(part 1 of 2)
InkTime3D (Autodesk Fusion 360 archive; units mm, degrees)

design "InkTime3D" references "Baterie", "WearAwareNewCase", "Shaker", "project-tsc", "Display_ePaper"
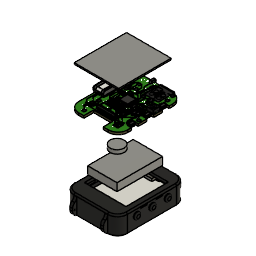
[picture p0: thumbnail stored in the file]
part number: 2026-04-19-21-12-50-660
component_insert "Component Insert1"
component_insert "Component Insert2"
component_insert "Component Insert3"
component_insert "Component Insert4"
component_insert "Component Insert5"

design "BST-BMV080-CAD"
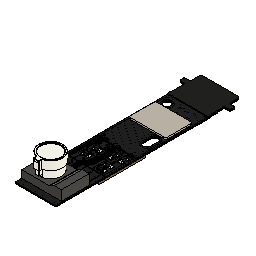
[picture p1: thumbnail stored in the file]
description: Part Number
part number: BMV080_MELTED
base_feature "Base Feature"

design "Display_ePaper"
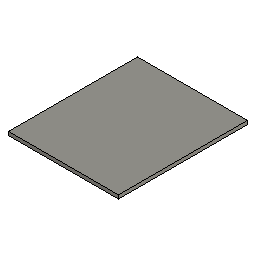
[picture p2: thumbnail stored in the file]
description: Part Number
part number: 2026-04-18-22-15-39-425
base_feature "Base Feature"

design "project-tsc"
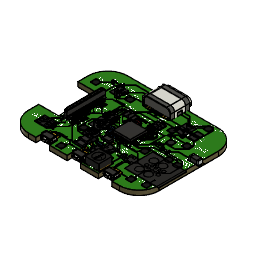
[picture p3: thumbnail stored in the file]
part number: 2026-04-17-17-33-59-124
part number: 2026-04-17-17-34-06-776
part number: 2026-04-17-17-34-07-423
part number: 2026-04-17-17-34-07-496
part number: 2026-04-17-17-34-07-570
part number: 2026-04-17-17-34-07-659
part number: 2026-04-17-17-34-07-837
part number: 2026-04-17-17-34-11-380
part number: 2026-04-17-17-34-11-386
part number: 2026-04-17-17-34-11-391
part number: 2026-04-17-17-34-11-420
part number: 2026-04-17-17-34-11-430
part number: 2026-04-17-17-34-11-437
part number: 2026-04-17-17-34-11-452
part number: 2026-04-17-17-34-11-458
part number: 2026-04-17-17-34-11-462
part number: 2026-04-17-17-34-11-469
part number: 2026-04-17-17-34-11-491
part number: 2026-04-17-17-34-11-533
part number: 2026-04-17-17-34-11-542
sketch "Outline" plane through (0, 0, 0) normal (0, 0, 1) x axis (1, 0, 0)
  line L1 (8.23, 32.71) -> (5.63, 32.71)
  line L2 (8.23, 34.51) -> (8.23, 32.71)
  line L3 (13.03, 34.51) -> (8.23, 34.51)
  line L4 (13.03, 32.71) -> (13.03, 34.51)
  line L5 (19.23, 32.71) -> (13.03, 32.71)
  line L6 (19.23, 34.51) -> (19.23, 32.71)
  line L7 (24.03, 34.51) -> (19.23, 34.51)
  line L8 (24.03, 32.71) -> (24.03, 34.51)
  line L9 (30.23, 32.71) -> (24.03, 32.71)
  line L10 (30.23, 34.51) -> (30.23, 32.71)
  line L11 (35.03, 34.51) -> (30.23, 34.51)
  line L12 (35.03, 32.71) -> (35.03, 34.51)
  line L13 (37.63, 32.71) -> (35.03, 32.71)
  line L14 (44.63, 60.71) -> (44.63, 39.71)
  line L15 (5.63, 67.71) -> (37.63, 67.71)
  line L16 (-1.37, 57.11) -> (-1.37, 60.71)
  line L17 (5.63, 57.11) -> (-1.37, 57.11)
  line L18 (5.63, 43.31) -> (5.63, 57.11)
  line L19 (-1.37, 43.31) -> (5.63, 43.31)
  line L20 (-1.37, 39.71) -> (-1.37, 43.31)
  line L21 (17.2539, 61.6177) -> (17.2526, 61.646)
  line L22 (17.2576, 61.5896) -> (17.2539, 61.6177)
  line L23 (17.2637, 61.5619) -> (17.2576, 61.5896)
  line L24 (17.2722, 61.5348) -> (17.2637, 61.5619)
  line L25 (17.2831, 61.5087) -> (17.2722, 61.5348)
  line L26 (17.2962, 61.4835) -> (17.2831, 61.5087)
  line L27 (17.3114, 61.4596) -> (17.2962, 61.4835)
  line L28 (17.3287, 61.4371) -> (17.3114, 61.4596)
  line L29 (17.3478, 61.4162) -> (17.3287, 61.4371)
  line L30 (17.3687, 61.397) -> (17.3478, 61.4162)
  line L31 (17.3912, 61.3798) -> (17.3687, 61.397)
  line L32 (17.4151, 61.3645) -> (17.3912, 61.3798)
  line L33 (17.4403, 61.3515) -> (17.4151, 61.3645)
  line L34 (17.4665, 61.3406) -> (17.4403, 61.3515)
  line L35 (17.4935, 61.3321) -> (17.4665, 61.3406)
  line L36 (17.5212, 61.3259) -> (17.4935, 61.3321)
  line L37 (17.5493, 61.3222) -> (17.5212, 61.3259)
  line L38 (17.5776, 61.321) -> (17.5493, 61.3222)
  line L39 (17.606, 61.3222) -> (17.5776, 61.321)
  line L40 (17.6341, 61.3259) -> (17.606, 61.3222)
  line L41 (17.6618, 61.3321) -> (17.6341, 61.3259)
  line L42 (17.6888, 61.3406) -> (17.6618, 61.3321)
  line L43 (17.715, 61.3515) -> (17.6888, 61.3406)
  line L44 (17.7401, 61.3645) -> (17.715, 61.3515)
  line L45 (17.764, 61.3798) -> (17.7401, 61.3645)
  line L46 (17.7865, 61.397) -> (17.764, 61.3798)
  line L47 (17.8074, 61.4162) -> (17.7865, 61.397)
  line L48 (17.8266, 61.4371) -> (17.8074, 61.4162)
  line L49 (17.8439, 61.4596) -> (17.8266, 61.4371)
  line L50 (17.8591, 61.4835) -> (17.8439, 61.4596)
  line L51 (17.8722, 61.5087) -> (17.8591, 61.4835)
  line L52 (17.883, 61.5348) -> (17.8722, 61.5087)
  line L53 (17.8916, 61.5619) -> (17.883, 61.5348)
  line L54 (17.8977, 61.5896) -> (17.8916, 61.5619)
  line L55 (17.9014, 61.6177) -> (17.8977, 61.5896)
  line L56 (17.9026, 61.646) -> (17.9014, 61.6177)
  line L57 (17.9026, 62.746) -> (17.9026, 61.646)
  line L58 (17.9014, 62.7743) -> (17.9026, 62.746)
  line L59 (17.8977, 62.8024) -> (17.9014, 62.7743)
  line L60 (17.8916, 62.8301) -> (17.8977, 62.8024)
  line L61 (17.883, 62.8572) -> (17.8916, 62.8301)
  line L62 (17.8722, 62.8834) -> (17.883, 62.8572)
  line L63 (17.8591, 62.9085) -> (17.8722, 62.8834)
  line L64 (17.8439, 62.9324) -> (17.8591, 62.9085)
  line L65 (17.8266, 62.9549) -> (17.8439, 62.9324)
  line L66 (17.8074, 62.9758) -> (17.8266, 62.9549)
  line L67 (17.7865, 62.995) -> (17.8074, 62.9758)
  line L68 (17.764, 63.0122) -> (17.7865, 62.995)
  line L69 (17.7401, 63.0275) -> (17.764, 63.0122)
  line L70 (17.715, 63.0406) -> (17.7401, 63.0275)
  line L71 (17.6888, 63.0514) -> (17.715, 63.0406)
  line L72 (17.6618, 63.0599) -> (17.6888, 63.0514)
  line L73 (17.6341, 63.0661) -> (17.6618, 63.0599)
  line L74 (17.606, 63.0698) -> (17.6341, 63.0661)
  line L75 (17.5776, 63.071) -> (17.606, 63.0698)
  line L76 (17.5493, 63.0698) -> (17.5776, 63.071)
  line L77 (17.5212, 63.0661) -> (17.5493, 63.0698)
  line L78 (17.4935, 63.0599) -> (17.5212, 63.0661)
  line L79 (17.4665, 63.0514) -> (17.4935, 63.0599)
  line L80 (17.4403, 63.0406) -> (17.4665, 63.0514)
  line L81 (17.4151, 63.0275) -> (17.4403, 63.0406)
  line L82 (17.3912, 63.0122) -> (17.4151, 63.0275)
  line L83 (17.3687, 62.995) -> (17.3912, 63.0122)
  line L84 (17.3478, 62.9758) -> (17.3687, 62.995)
  line L85 (17.3287, 62.9549) -> (17.3478, 62.9758)
  line L86 (17.3114, 62.9324) -> (17.3287, 62.9549)
  line L87 (17.2962, 62.9085) -> (17.3114, 62.9324)
  line L88 (17.2831, 62.8834) -> (17.2962, 62.9085)
  line L89 (17.2722, 62.8572) -> (17.2831, 62.8834)
  line L90 (17.2637, 62.8301) -> (17.2722, 62.8572)
  line L91 (17.2576, 62.8024) -> (17.2637, 62.8301)
  line L92 (17.2539, 62.7743) -> (17.2576, 62.8024)
  line L93 (17.2526, 62.746) -> (17.2539, 62.7743)
  line L94 (17.2526, 61.646) -> (17.2526, 62.746)
  line L95 (25.8939, 61.6177) -> (25.8926, 61.646)
  line L96 (25.8976, 61.5896) -> (25.8939, 61.6177)
  line L97 (25.9037, 61.5619) -> (25.8976, 61.5896)
  line L98 (25.9122, 61.5348) -> (25.9037, 61.5619)
  line L99 (25.9231, 61.5087) -> (25.9122, 61.5348)
  line L100 (25.9362, 61.4835) -> (25.9231, 61.5087)
  line L101 (25.9514, 61.4596) -> (25.9362, 61.4835)
  line L102 (25.9687, 61.4371) -> (25.9514, 61.4596)
  line L103 (25.9878, 61.4162) -> (25.9687, 61.4371)
  line L104 (26.0087, 61.397) -> (25.9878, 61.4162)
  line L105 (26.0312, 61.3798) -> (26.0087, 61.397)
  line L106 (26.0551, 61.3645) -> (26.0312, 61.3798)
  line L107 (26.0803, 61.3515) -> (26.0551, 61.3645)
  line L108 (26.1065, 61.3406) -> (26.0803, 61.3515)
  line L109 (26.1335, 61.3321) -> (26.1065, 61.3406)
  line L110 (26.1612, 61.3259) -> (26.1335, 61.3321)
  line L111 (26.1893, 61.3222) -> (26.1612, 61.3259)
  line L112 (26.2176, 61.321) -> (26.1893, 61.3222)
  line L113 (26.246, 61.3222) -> (26.2176, 61.321)
  line L114 (26.2741, 61.3259) -> (26.246, 61.3222)
  line L115 (26.3017, 61.3321) -> (26.2741, 61.3259)
  line L116 (26.3288, 61.3406) -> (26.3017, 61.3321)
  line L117 (26.355, 61.3515) -> (26.3288, 61.3406)
  line L118 (26.3801, 61.3645) -> (26.355, 61.3515)
  line L119 (26.404, 61.3798) -> (26.3801, 61.3645)
  line L120 (26.4265, 61.397) -> (26.404, 61.3798)
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canvas "Canvas1" bodies "Board"
canvas "Canvas2" bodies "Board"
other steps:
base_feature "Base Feature1"
base_feature "Base Feature1"
base_feature "Base Feature1"
base_feature "Base Feature1"
base_feature "Base Feature1"
base_feature "Base Feature1"
base_feature "Base Feature1"
base_feature "Base Feature1"
base_feature "Base Feature1"
base_feature "Base Feature1"
base_feature "Base Feature1"
base_feature "Base Feature1"
base_feature "Base Feature1"
base_feature "Base Feature1"
base_feature "Base Feature1"
base_feature "Base Feature1"
base_feature "Base Feature1"
base_feature "Base Feature1"
base_feature "Base Feature1"
base_feature "Base Feature1"
base_feature "Base Feature1"
base_feature "Base Feature1"
base_feature "Base Feature1"
base_feature "Base Feature1"
base_feature "Base Feature1"
base_feature "Base Feature1"
base_feature "Base Feature1"
base_feature "Base Feature1"
base_feature "Base Feature1"
base_feature "Base Feature1"
base_feature "Base Feature1"
base_feature "Base Feature1"
base_feature "Base Feature1"
base_feature "Base Feature1"
pcbextrude "PCBExtrude1"
box_primitive "BoxPrimitive1" DistanceX 4.1 DistanceY 4.6 DistanceZ 0.1 OffsetDistanceX 0 OffsetDistanceY 0
box_primitive "BoxPrimitive1" DistanceX 3.08 DistanceY 3.63 DistanceZ 0.1 OffsetDistanceX 0 OffsetDistanceY 0
box_primitive "BoxPrimitive1" DistanceX 0.35 DistanceY 0.8 DistanceZ 0.1 OffsetDistanceX 0 OffsetDistanceY 0
box_primitive "BoxPrimitive1" DistanceX 3.52 DistanceY 3.52 DistanceZ 0.1 OffsetDistanceX 0 OffsetDistanceY 0
box_primitive "BoxPrimitive1" DistanceX 4.25 DistanceY 3.6 DistanceZ 0.1 OffsetDistanceX 0 OffsetDistanceY 0
box_primitive "BoxPrimitive1" DistanceX 3.003 DistanceY 3 DistanceZ 0.1 OffsetDistanceX 0 OffsetDistanceY 0
box_primitive "BoxPrimitive1" DistanceX 3.7 DistanceY 2.75 DistanceZ 0.1 OffsetDistanceX 0 OffsetDistanceY 0
box_primitive "BoxPrimitive1" DistanceX 3.454 DistanceY 2.184 DistanceZ 0.1 OffsetDistanceX 0 OffsetDistanceY 0
box_primitive "BoxPrimitive1" DistanceX 3.785 DistanceY 2.65 DistanceZ 0.1 OffsetDistanceX 0 OffsetDistanceY 0
box_primitive "BoxPrimitive1" DistanceX 1.142 DistanceY 0.776 DistanceZ 0.1 OffsetDistanceX 0 OffsetDistanceY 0
box_primitive "BoxPrimitive1" DistanceX 2 DistanceY 2 DistanceZ 0.1 OffsetDistanceX 0 OffsetDistanceY 0
box_primitive "BoxPrimitive1" DistanceX 3.45 DistanceY 2.35 DistanceZ 0.1 OffsetDistanceX 0 OffsetDistanceY 0
box_primitive "BoxPrimitive1" DistanceX 4.1 DistanceY 2.4 DistanceZ 0.1 OffsetDistanceX 0 OffsetDistanceY 0
box_primitive "BoxPrimitive1" DistanceX 1.8 DistanceY 0.9 DistanceZ 0.1 OffsetDistanceX 0 OffsetDistanceY 0
box_primitive "BoxPrimitive1" DistanceX 1.1 DistanceY 0.7 DistanceZ 0.1 OffsetDistanceX 0 OffsetDistanceY 0
box_primitive "BoxPrimitive1" DistanceX 1.4 DistanceY 0.8 DistanceZ 0.1 OffsetDistanceX 0 OffsetDistanceY 0
box_primitive "BoxPrimitive1" DistanceX 2.1 DistanceY 1 DistanceZ 0.1 OffsetDistanceX 0 OffsetDistanceY 0
box_primitive "BoxPrimitive1" DistanceX 3.2 DistanceY 2.7 DistanceZ 0.1 OffsetDistanceX 0 OffsetDistanceY 0
box_primitive "BoxPrimitive1" DistanceX 3.49 DistanceY 4.39 DistanceZ 0.1 OffsetDistanceX 0 OffsetDistanceY 0
box_primitive "BoxPrimitive1" DistanceX 12 DistanceY 9.9 DistanceZ 0.1 OffsetDistanceX 0 OffsetDistanceY 0
pcbextrude "PCBExtrude1"
pcbextrude "PCBExtrude1"
pcbextrude "PCBExtrude1"
pcbhole "PCBHole2"
pcbhole "PCBHole2"
pcbhole "PCBHole3"
pcbhole "PCBHole3"
extrude "Extrude1" sketch "Outline" blind 1.6 bodies "Board"
pcbextrude "PCBExtrude1"
pcbextrude "PCBExtrude2" bodies "CopperHoles"
pcbhole "PCBHole2"
pcbhole "PCBHole3"
create_component "CreateComponent1"
create_component "CreateComponent2"
create_component "CreateComponent3"
create_component "CreateComponent4"
create_component "CreateComponent5"
create_component "CreateComponent6"
create_component "CreateComponent4"
create_component "CreateComponent5"
create_component "CreateComponent6"
create_component "CreateComponent7"
create_component "CreateComponent9"
create_component "CreateComponent10"
create_component "CreateComponent12"
create_component "CreateComponent13"
create_component "CreateComponent14"
create_component "CreateComponent15"
create_component "CreateComponent16"
create_component "CreateComponent18"
create_component "CreateComponent19"
create_component "CreateComponent20"
create_component "CreateComponent21"
create_component "CreateComponent22"
create_component "CreateComponent23"
create_component "CreateComponent25"
create_component "CreateComponent26"
create_component "CreateComponent27"
as_built_joint "As-built1"
create_component "CreateComponent28"
create_component "CreateComponent1"
create_component "CreateComponent29"
create_component "CreateComponent1"
create_component "CreateComponent30"
create_component "CreateComponent1"
create_component "CreateComponent31"
create_component "CreateComponent1"
create_component "CreateComponent1"
create_component "CreateComponent2"
create_component "CreateComponent3"
create_component "CreateComponent33"
create_component "CreateComponent1"
create_component "CreateComponent34"
create_component "CreateComponent1"
create_component "CreateComponent1"
create_component "CreateComponent2"
create_component "CreateComponent3"
create_component "CreateComponent4"
create_component "CreateComponent5"
create_component "CreateComponent6"
create_component "CreateComponent35"
create_component "CreateComponent1"
create_component "CreateComponent36"
create_component "CreateComponent1"
create_component "CreateComponent37"
create_component "CreateComponent1"
create_component "CreateComponent38"
create_component "CreateComponent1"
create_component "CreateComponent1"
create_component "CreateComponent2"
create_component "CreateComponent3"
create_component "CreateComponent39"
create_component "CreateComponent1"
named bodies: "Board", "CopperHoles"

design "WearAwareNewCase" references "BST-BMV080-CAD"
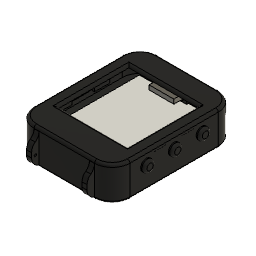
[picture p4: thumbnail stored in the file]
sketch "Sketch1" plane through (0, 0, 0) normal (0, 0, 1) x axis (1, 0, 0)
  line L1 (-19, -24.5) -> (19, -24.5)
  line L2 (-19, 24.5) -> (-19, -24.5)
  line L3 (19, 24.5) -> (-19, 24.5)
  line L4 (19, -24.5) -> (19, 24.5)
  line L5 (-19, 24.5) -> (19, -24.5)
  line L6 (19, 24.5) -> (-19, -24.5)
  point P6 (0, 0)
  point P1 (0, 0)
  point P4 (-19, 24.5)
  point P5 (19, 24.5)
  point P3 (-19, -24.5)
  horizontal L1
  perpendicular L1 L2
  parallel L1 L3
  parallel L2 L4
  coincident L5 P6
  coincident L6 P6
  coincident P1 P6
  dimension "d1" distance P4 P5 = 38
  dimension "d2" distance P3 P4 = 49
extrude "Extrude1" new body sketch "Sketch1" profile of L1 L2 L3 L4 along normal blind 2
fillet "Fillet1" radius 7
sketch "Sketch2" plane through (0, 0, 2) normal (0, 0, 1) x axis (-1, 0, 0)
  line L1 (19, 17.5) -> (19, -17.5)
  line L2 (-12, 24.5) -> (12, 24.5)
  line L3 (-19, -17.5) -> (-19, 17.5)
  line L4 (12, -24.5) -> (-12, -24.5)
  line L5 (18, -23.5) -> (-18, -23.5)
  line L6 (18, 23.5) -> (18, -23.5)
  line L7 (-18, 23.5) -> (18, 23.5)
  line L8 (-18, -23.5) -> (-18, 23.5)
  line L9 (18, 23.5) -> (-18, -23.5)
  line L10 (-18, 23.5) -> (18, -23.5)
  arc A1 centre (12, -17.5) radius 7 clockwise from (19, -17.5) to (12, -24.5)
  arc A2 centre (12, 17.5) radius 7 clockwise from (12, 24.5) to (19, 17.5)
  arc A3 centre (-12, 17.5) radius 7 clockwise from (-19, 17.5) to (-12, 24.5)
  arc A4 centre (-12, -17.5) radius 7 clockwise from (-12, -24.5) to (-19, -17.5)
  point P18 (0, 0)
  point P1 (0, 0)
  point P16 (18, 23.5)
  point P17 (-18, 23.5)
  point P15 (18, -23.5)
  horizontal L5
  perpendicular L5 L6
  parallel L5 L7
  parallel L6 L8
  coincident L9 P18
  coincident L10 P18
  coincident P1 P18
  dimension "d7" distance P16 P17 = 36
  dimension "d8" distance P15 P16 = 47
extrude "Extrude2" new body sketch "Sketch2" profile of A1 A2 A3 A4 L5 L6 L7 L8 along normal blind 2
fillet "Fillet2" radius 7
move "Move1"
extrude "Extrude3" add of existing geometry blind 2
extrude "Extrude4" cut of existing geometry blind 20
sketch "Sketch3" plane through (0, 0, 0) normal (0, 0, 1) x axis (1, 0, 0)
  line L1 (-18.75, -15.5) -> (18.75, -15.5)
  line L2 (-18.75, 15.5) -> (-18.75, -15.5)
  line L3 (18.75, 15.5) -> (-18.75, 15.5)
  line L4 (18.75, -15.5) -> (18.75, 15.5)
  line L5 (-18.75, 15.5) -> (18.75, -15.5)
  line L6 (18.75, 15.5) -> (-18.75, -15.5)
  point P6 (0, 0)
  point P1 (0, 0)
  point P4 (-18.75, 15.5)
  point P5 (18.75, 15.5)
  point P3 (-18.75, -15.5)
  horizontal L1
  perpendicular L1 L2
  parallel L1 L3
  parallel L2 L4
  coincident L5 P6
  coincident L6 P6
  coincident P1 P6
  dimension "d17" distance P4 P5 = 37.5
  dimension "d18" distance P3 P4 = 31
extrude "Extrude5" new body sketch "Sketch3" profile of L1 L2 L3 L4 along normal blind 4.5 bodies "Battery"
move "Move2"
move "Move3"
align "Align1"
extrude "Extrude6" add of existing geometry blind 2.5
remove_body "RemoveBody1"
move "Move4"
move "Move5"
extrude "Extrude7" add of existing geometry blind 1
extrude "Extrude8" add of existing geometry blind 4.5
extrude "Extrude9" cut of existing geometry blind 20
move "Move6"
sketch "Sketch4" plane through (0, -16.75, 0) normal (0, 1, 0) x axis (-1, 0, 0)
  line L1 (-15.5, 6.5) -> (15.5, 6.5)
  line L2 (-15.5, 2) -> (-15.5, 6.5)
  line L3 (15.5, 2) -> (-15.5, 2)
  line L4 (15.5, 6.5) -> (15.5, 2)
  line L5 (15.5, 6.5) -> (0, 6.5)
  line L6 (15.5, 2) -> (15.5, 6.5)
  line L7 (0, 2) -> (15.5, 2)
  line L8 (0, 6.5) -> (0, 2)
  point P5 (15.5, 2)
  point P8 (15.5, 2)
  point P6 (0, 6.5)
  horizontal L5
  vertical L6
  horizontal L7
  vertical L8
  coincident P5 P8
  midpoint L1 P6
extrude "Extrude10" cut sketch "Sketch4" profile of L1 L3 L4 L5 L6 L7 L8 against normal blind 5
sketch "Sketch5" plane through (0, 0, 6.5) normal (0, 0, 1) x axis (-1, 0, 0)
  line L1 (18, 16.5) -> (18, -16.5)
  line L2 (-11, 23.5) -> (11, 23.5)
  line L3 (-18, -16.5) -> (-18, 16.5)
  line L4 (11, -23.5) -> (-11, -23.5)
  line L5 (0, 21.75) -> (0, 16.75)
  line L6 (15.5, 21.75) -> (0, 21.75)
  line L7 (15.5, -20.75) -> (15.5, 21.75)
  line L8 (-15.5, -20.75) -> (15.5, -20.75)
  line L9 (-15.5, 16.75) -> (-15.5, -20.75)
  line L10 (0, 16.75) -> (-15.5, 16.75)
  line L11 (17.9999, 16.5317) -> (15.5, 16.5317)
  line L12 (15.5, 16.5317) -> (15.5, 21.75)
  line L13 (15.5, 21.8619) -> (15.5, 21.75)
  line L14 (15.5, 16.5317) -> (15.5, 21.8619)
  arc A1 centre (11, -16.5) radius 7 clockwise from (18, -16.5) to (11, -23.5)
  arc A2 centre (11, 16.5) radius 7 clockwise from (11, 23.5) to (18, 16.5)
  arc A3 centre (-11, 16.5) radius 7 clockwise from (-18, 16.5) to (-11, 23.5)
  arc A4 centre (-11, -16.5) radius 7 clockwise from (-11, -23.5) to (-18, -16.5)
  point P20 (15.5, 16.5317)
  point P21 (17.9999, 16.5317)
  point P16 (15.5, 21.75)
  point P22 (15.5, 21.75)
  point P23 (15.5, 21.8619)
  coincident L7 P20
  coincident A2 P21
  perpendicular L7 L11
  coincident P16 P22
  coincident A2 P23
  perpendicular L6 L13
extrude "Extrude11" cut sketch "Sketch5" profile of A2 L7 L11 L12 L13 L14 against normal blind 4.5
sketch "Sketch6" plane through (0, 0, 6.5) normal (0, 0, 1) x axis (-1, 0, 0)
  line L1 (15.5, 16.5317) -> (17.9999, 16.5317)
  line L2 (15.5, -20.75) -> (15.5, 16.5317)
  line L3 (-15.5, -20.75) -> (15.5, -20.75)
  line L4 (-15.5, 16.75) -> (-15.5, -20.75)
  line L5 (0, 16.75) -> (-15.5, 16.75)
  line L6 (0, 21.75) -> (0, 16.75)
  line L7 (15.5, 21.75) -> (0, 21.75)
  line L8 (15.5, 21.8619) -> (15.5, 21.75)
  line L9 (-11, 23.5) -> (11, 23.5)
  line L10 (-18, -16.5) -> (-18, 16.5)
  line L11 (11, -23.5) -> (-11, -23.5)
  line L12 (18, 16.5) -> (18, -16.5)
  line L13 (10.7244, 21.75) -> (10.7244, 23.5)
  arc A1 centre (11, 16.5) radius 7 clockwise from (11, 23.5) to (15.5, 21.8619)
  arc A2 centre (-11, 16.5) radius 7 clockwise from (-18, 16.5) to (-11, 23.5)
  arc A3 centre (-11, -16.5) radius 7 clockwise from (-11, -23.5) to (-18, -16.5)
  arc A4 centre (11, -16.5) radius 7 clockwise from (18, -16.5) to (11, -23.5)
  arc A5 centre (11, 16.5) radius 7 clockwise from (17.9999, 16.5317) to (18, 16.5)
  point P23 (10.7244, 23.5)
  point P24 (10.7244, 21.75)
  coincident L9 P23
  coincident L7 P24
  perpendicular L7 L13
extrude "Extrude12" cut sketch "Sketch6" profile of L7 L8 A1 L9 L13 against normal blind 4.5
extrude "Extrude13" add of existing geometry blind 4
extrude "Extrude14" cut of existing geometry blind 6.5
extrude "Extrude15" cut of existing geometry blind -0.1
extrude "Extrude16" cut of existing geometry blind -5
extrude "Extrude17" cut of existing geometry blind -3.6
sketch "Sketch7" plane through (0, 0, 6.5) normal (0, 0, 1) x axis (-1, 0, 0)
  line L1 (10.7244, 23.5) -> (10.7244, 21.75)
  line L2 (-11, 23.5) -> (10.7244, 23.5)
  line L3 (-18, -16.5) -> (-18, 16.5)
  line L4 (11, -23.5) -> (-11, -23.5)
  line L5 (18, 16.5) -> (18, -16.5)
  line L6 (15.5, 16.5317) -> (17.9999, 16.5317)
  line L7 (15.5, -20.75) -> (15.5, 16.5317)
  line L8 (-15.5, -20.75) -> (15.5, -20.75)
  line L9 (-15.5, 16.75) -> (-15.5, -20.75)
  line L10 (0, 16.75) -> (-15.5, 16.75)
  line L11 (0, 21.75) -> (0, 16.75)
  line L12 (10.7244, 21.75) -> (0, 21.75)
  line L13 (-18, 2.4) -> (-17.5, 2.4)
  line L14 (-18, 8.6) -> (-18, 2.4)
  line L15 (-17.5, 8.6) -> (-18, 8.6)
  line L16 (-17.5, 2.4) -> (-17.5, 8.6)
  line L17 (-17.5, 2.4) -> (-18, 2.4)
  line L18 (-17.5, 8.6) -> (-17.5, 2.4)
  line L19 (-18, 8.6) -> (-17.5, 8.6)
  line L20 (-18, 2.4) -> (-18, 8.6)
  line L21 (-18, -2.4) -> (-17.5, -2.4)
  line L22 (-18, -8.6) -> (-18, -2.4)
  line L23 (-17.5, -2.4) -> (-17.5, -8.6)
  line L24 (-18, -8.6) -> (-17.5, -8.6)
  arc A1 centre (-11, 16.5) radius 7 clockwise from (-18, 16.5) to (-11, 23.5)
  arc A2 centre (-11, -16.5) radius 7 clockwise from (-11, -23.5) to (-18, -16.5)
  arc A3 centre (11, -16.5) radius 7 clockwise from (18, -16.5) to (11, -23.5)
  arc A4 centre (11, 16.5) radius 7 clockwise from (17.9999, 16.5317) to (18, 16.5)
  point P24 (-18, 8.6)
  point P29 (-18, -2.4)
  point P30 (-18, -8.6)
  horizontal L13
  vertical L14
  horizontal L15
  vertical L16
  coincident L3 P24
  horizontal L17
  vertical L18
  horizontal L19
  vertical L20
  coincident L3 P29
  perpendicular L3 L21
  coincident L3 P30
  perpendicular L21 L23
  perpendicular L22 L24
extrude "Extrude18" add sketch "Sketch7" profile of L3 L13 L14 L15 L16 L17 L18 L19 L20 L21 L22 L23 L24 along normal blind 3
sketch "Sketch8" plane through (0, 0, 0) normal (0, 0, 1) x axis (1, 0, 0)
  line L1 (19, -24.5) -> (-19, -24.5)
  line L2 (19, 24.5) -> (19, -24.5)
  line L3 (-19, 24.5) -> (19, 24.5)
  line L4 (-19, -24.5) -> (-19, 24.5)
  line L5 (19, 24.5) -> (-19, -24.5)
  line L6 (-19, 24.5) -> (19, -24.5)
  point P6 (0, 0)
  point P1 (0, 0)
  point P4 (19, 24.5)
  point P5 (-19, 24.5)
  point P3 (19, -24.5)
  horizontal L1
  perpendicular L1 L2
  parallel L1 L3
  parallel L2 L4
  coincident L5 P6
  coincident L6 P6
  coincident P1 P6
  dimension "d47" distance P4 P5 = 38
  dimension "d48" distance P3 P4 = 49
extrude "Extrude19" new body sketch "Sketch8" profile of L1 L2 L3 L4 along normal blind 2 bodies "TopCase"
move "Move7"
fillet "Fillet3" radius 7
extrude "Extrude20" cut of existing geometry blind 14
move "Move8"
extrude "Extrude21" add of existing geometry blind 0.5
extrude "Extrude22" cut of existing geometry blind -25
component_insert "Component Insert"
sketch "Sketch9" plane through (16.4792, 0, 0) normal (1, 0, 0) x axis (0, 1, 0)
  line L1 (-11.55, 7.93) -> (-11.55, 8.53)
  line L2 (-10.45, 7.93) -> (-11.55, 7.93)
  line L3 (-10.45, 8.53) -> (-10.45, 7.93)
  line L4 (-11.55, 8.53) -> (-10.45, 8.53)
  line L5 (-13.3, 6.5) -> (-8.7, 6.5)
  line L6 (-13.3, 9.9) -> (-13.3, 6.5)
  line L7 (-8.7, 9.9) -> (-13.3, 9.9)
  line L8 (-8.7, 6.5) -> (-8.7, 9.9)
  line L9 (-13.3, 9.9) -> (-8.7, 6.5)
  line L10 (-8.7, 9.9) -> (-13.3, 6.5)
  point P10 (-11, 8.2)
  point P8 (-13.3, 9.9)
  point P9 (-8.7, 9.9)
  horizontal L5
  perpendicular L5 L6
  parallel L5 L7
  parallel L6 L8
  coincident L9 P10
  coincident L10 P10
  dimension "d59" distance P8 P9 = 4.6
extrude "Extrude23" new body sketch "Sketch9" profile of L1 L2 L3 L4 L5 L6 L7 L8 along normal blind 1 bodies "Button1"
extrude "Extrude24" add of existing geometry blind 1.2
extrude "Extrude25" add of existing geometry blind 1.2
sketch "Sketch10" plane through (17.4792, 0, 0) normal (1, 0, 0) x axis (0, 1, 0)
  line L1 (-13.3, 6.5) -> (-13.3, 11.1)
  line L2 (-8.7, 6.5) -> (-13.3, 6.5)
  line L3 (-8.7, 11.1) -> (-8.7, 6.5)
  line L4 (-13.3, 11.1) -> (-8.7, 11.1)
  circle C1 centre (-11, 8.8) radius 2.25
  dimension "d66" diameter C1 = 4.5
extrude "Extrude26" cut sketch "Sketch10" profile of C1 along normal blind 10
extrude "Extrude27" add sketch "Sketch10" profile of C1 along normal blind 4
extrude "Extrude28" cut of existing geometry blind -1
fillet "Fillet4" radius 1
copy_paste_bodies "CopyPasteBodies1"
move "Move9"
copy_paste_bodies "CopyPasteBodies2"
move "Move10"
sketch "Sketch11" plane through (20.4792, 0, 0) normal (1, 0, 0) x axis (0, 1, 0)
  circle C1 centre (0, 8.8) radius 1.25
  circle C2 centre (0, 8.8) radius 2.25
  concentric C1 C2
  dimension "d75" diameter C2 = 4.5
sketch "Sketch12" plane through (20.4792, 0, 0) normal (1, 0, 0) x axis (0, 1, 0)
  circle C1 centre (11, 8.8) radius 1.25
  circle C2 centre (11, 8.8) radius 2.25
  concentric C1 C2
  dimension "d76" diameter C2 = 4.5
extrude "Extrude29" cut sketch "Sketch11" + "Sketch12" blind -3
sketch "Sketch13" plane through (0, 0, 12) normal (0, 0, -1) x axis (1, 0, 0)
  line L1 (13.6766, -14.925) -> (13.6766, 13.2436)
  line L2 (-13.9332, -14.925) -> (13.6766, -14.925)
  line L3 (-13.9332, 13.2436) -> (-13.9332, -14.925)
  line L4 (13.6766, 13.2436) -> (-13.9332, 13.2436)
  line L5 (12, -24.5) -> (-12, -24.5)
  line L6 (19, 17.5) -> (19, -17.5)
  line L7 (-12, 24.5) -> (12, 24.5)
  line L8 (-19, -17.5) -> (-19, 17.5)
  line L9 (18, -23.5) -> (-18, -23.5)
  line L10 (18, 23.5) -> (18, -23.5)
  line L11 (-18, 23.5) -> (18, 23.5)
  line L12 (-18, -23.5) -> (-18, 23.5)
  line L13 (18, 23.5) -> (-18, -23.5)
  line L14 (-18, 23.5) -> (18, -23.5)
  arc A1 centre (-12, -17.5) radius 7 clockwise from (-12, -24.5) to (-19, -17.5)
  arc A2 centre (12, -17.5) radius 7 clockwise from (19, -17.5) to (12, -24.5)
  arc A3 centre (12, 17.5) radius 7 clockwise from (12, 24.5) to (19, 17.5)
  arc A4 centre (-12, 17.5) radius 7 clockwise from (-19, 17.5) to (-12, 24.5)
  point P22 (0, 0)
  point P1 (0, 0)
  point P20 (18, 23.5)
  point P21 (-18, 23.5)
  point P19 (18, -23.5)
  horizontal L9
  perpendicular L9 L10
  parallel L9 L11
  parallel L10 L12
  coincident L13 P22
  coincident L14 P22
  coincident P1 P22
  dimension "d79" distance P20 P21 = 36
  dimension "d80" distance P19 P20 = 47
extrude "Extrude30" new body sketch "Sketch13" profile of L1 L2 L3 L4 A1 A2 A3 A4 L9 L10 L11 L12 along normal blind 1
fillet "Fillet5" radius 7
sketch "Sketch14" plane through (0, 0, 11) normal (0, 0, -1) x axis (1, 0, 0)
  line L1 (-18, -16.5) -> (-18, 16.5)
  line L2 (11, -23.5) -> (-11, -23.5)
  line L3 (18, 16.5) -> (18, -16.5)
  line L4 (-11, 23.5) -> (11, 23.5)
  line L5 (-13.9332, 13.2436) -> (-13.9332, -14.925)
  line L6 (13.6766, 13.2436) -> (-13.9332, 13.2436)
  line L7 (13.6766, -14.925) -> (13.6766, 13.2436)
  line L8 (-13.9332, -14.925) -> (13.6766, -14.925)
  line L9 (17, -22.5) -> (-17, -22.5)
  line L10 (17, 22.5) -> (17, -22.5)
  line L11 (-17, 22.5) -> (17, 22.5)
  line L12 (-17, -22.5) -> (-17, 22.5)
  line L13 (17, 22.5) -> (-17, -22.5)
  line L14 (-17, 22.5) -> (17, -22.5)
  arc A1 centre (-11, 16.5) radius 7 clockwise from (-18, 16.5) to (-11, 23.5)
  arc A2 centre (-11, -16.5) radius 7 clockwise from (-11, -23.5) to (-18, -16.5)
  arc A3 centre (11, -16.5) radius 7 clockwise from (18, -16.5) to (11, -23.5)
  arc A4 centre (11, 16.5) radius 7 clockwise from (11, 23.5) to (18, 16.5)
  point P22 (0, 0)
  point P1 (0, 0)
  point P20 (17, 22.5)
  point P21 (-17, 22.5)
  point P19 (17, -22.5)
  horizontal L9
  perpendicular L9 L10
  parallel L9 L11
  parallel L10 L12
  coincident L13 P22
  coincident L14 P22
  coincident P1 P22
  dimension "d85" distance P20 P21 = 34
  dimension "d86" distance P19 P20 = 45
extrude "Extrude31" new body sketch "Sketch14" profile of A1 A2 A3 A4 L5 L6 L7 L8 L9 L10 L11 L12 along normal blind 1
fillet "Fillet6" radius 7
extrude "Extrude32" cut of existing geometry blind -6
combine "Combine1" bodies "TopCase"
remove_instance "RemoveInstance1"
extrude "Extrude33" add of existing geometry blind 0.6
extrude "Extrude34" cut of existing geometry blind -0.6
extrude "Extrude35" cut of existing geometry blind 25 bodies "TopCase (1)"
remove_body "RemoveBody2"
extrude "Extrude36" cut of existing geometry blind 12
extrude "Extrude37" cut of existing geometry blind 5
extrude "Extrude38" cut of existing geometry blind 20
sketch "Sketch15" plane through (0, 0, 11) normal (0, 0, -1) x axis (1, 0, 0)
  line L1 (-10, -22.5) -> (10, -22.5)
  line L2 (-17, 15.5) -> (-17, -15.5)
  line L3 (10, 22.5) -> (-10, 22.5)
  line L4 (17, -15.5) -> (17, 15.5)
  line L5 (-18, -16.5) -> (-18, 16.5)
  line L6 (11, -23.5) -> (-11, -23.5)
  line L7 (18, 16.5) -> (18, -16.5)
  line L8 (-11, 23.5) -> (11, 23.5)
  line L9 (18, 8.6) -> (17, 8.6)
  line L10 (18, 2.4) -> (17, 2.4)
  line L11 (18, -2.4) -> (17, -2.4)
  line L12 (18, -8.6) -> (17, -8.6)
  line L13 (12.0273, -22.2) -> (12.9, -22.2)
  line L14 (12.9, -22.2) -> (12.9, -21.871)
  arc A1 centre (-10, -15.5) radius 7 clockwise from (-10, -22.5) to (-17, -15.5)
  arc A2 centre (-10, 15.5) radius 7 clockwise from (-17, 15.5) to (-10, 22.5)
  arc A3 centre (10, 15.5) radius 7 clockwise from (10, 22.5) to (17, 15.5)
  arc A4 centre (10, -15.5) radius 7 clockwise from (12.0273, -22.2) to (10, -22.5)
  arc A5 centre (-11, 16.5) radius 7 clockwise from (-18, 16.5) to (-11, 23.5)
  arc A6 centre (-11, -16.5) radius 7 clockwise from (-11, -23.5) to (-18, -16.5)
  arc A7 centre (11, -16.5) radius 7 clockwise from (18, -16.5) to (11, -23.5)
  arc A8 centre (11, 16.5) radius 7 clockwise from (11, 23.5) to (18, 16.5)
  arc A9 centre (10, -15.5) radius 7 clockwise from (17, -15.5) to (12.9, -21.871)
  point P27 (17, 8.6)
  point P28 (18, 8.6)
  point P29 (17, 2.4)
  point P30 (18, 2.4)
  point P31 (17, -2.4)
  point P32 (18, -2.4)
  point P33 (17, -8.6)
  point P34 (18, -8.6)
  coincident L4 P27
  coincident L7 P28
  perpendicular L7 L9
  coincident L4 P29
  coincident L7 P30
  perpendicular L7 L10
  coincident L4 P31
  coincident L7 P32
  perpendicular L7 L11
  coincident L4 P33
  coincident L7 P34
  perpendicular L7 L12
extrude "Extrude39" add sketch "Sketch15" profile of L4 L7 L9 L10 L11 L12 along normal blind 3.5
extrude "Extrude40" cut of existing geometry blind -2.5
extrude "Extrude41" cut of existing geometry blind -2.5
extrude "Extrude42" add of existing geometry blind 0.4
extrude "Extrude43" add of existing geometry blind 0.4
sketch "Sketch16" plane through (0, 0, 11) normal (0, 0, -1) x axis (1, 0, 0)
  line L1 (-10, -22.5) -> (10, -22.5)
  line L2 (-17, 15.5) -> (-17, -15.5)
  line L3 (10, 22.5) -> (-10, 22.5)
  line L4 (17, -15.5) -> (17, -8.6)
  line L5 (-11, 23.5) -> (11, 23.5)
  line L6 (-18, -16.5) -> (-18, 16.5)
  line L7 (11, -23.5) -> (-11, -23.5)
  line L8 (18, 16.5) -> (18, 8.6)
  line L9 (-18, -10.5) -> (-18, -4.5)
  line L10 (-17, -10.5) -> (-18, -10.5)
  line L11 (-17, -4.5) -> (-18, -4.5)
  line L12 (-17, -10.5) -> (-17, -4.5)
  line L13 (-17, 4.5) -> (-18, 4.5)
  line L14 (-18, 4.6) -> (-18, 4.5)
  line L15 (-18, 10.5) -> (-18, 4.5)
  line L16 (-17, 10.5) -> (-18, 10.5)
  line L17 (-17, 10.5) -> (-17, 4.5)
  line L18 (17, -8.6) -> (18, -8.6)
  line L19 (12.9, -22.2) -> (12.9, -21.871)
  line L20 (12.0273, -22.2) -> (12.9, -22.2)
  line L21 (18, 8.6) -> (17, 8.6)
  line L22 (17, 8.6) -> (17, 15.5)
  line L23 (18, -8.6) -> (18, -16.5)
  arc A1 centre (10, -15.5) radius 7 clockwise from (17, -15.5) to (12.9, -21.871)
  arc A2 centre (-10, -15.5) radius 7 clockwise from (-10, -22.5) to (-17, -15.5)
  arc A3 centre (-10, 15.5) radius 7 clockwise from (-17, 15.5) to (-10, 22.5)
  arc A4 centre (10, 15.5) radius 7 clockwise from (10, 22.5) to (17, 15.5)
  arc A5 centre (11, 16.5) radius 7 clockwise from (11, 23.5) to (18, 16.5)
  arc A6 centre (-11, 16.5) radius 7 clockwise from (-18, 16.5) to (-11, 23.5)
  arc A7 centre (-11, -16.5) radius 7 clockwise from (-11, -23.5) to (-18, -16.5)
  arc A8 centre (11, -16.5) radius 7 clockwise from (18, -16.5) to (11, -23.5)
  arc A9 centre (10, -15.5) radius 7 clockwise from (12.0273, -22.2) to (10, -22.5)
  point P29 (-18, -4.5)
  point P31 (-17, -10.5)
  point P33 (-18, 4.5)
  point P35 (-18, 4.6)
  point P37 (-17, 10.5)
  point P30 (-18, -10.5)
  point P32 (-17, -4.5)
  point P34 (-17, 4.5)
  point P36 (-18, 10.5)
  coincident L6 P29
  coincident L2 P31
  perpendicular L2 L10
  perpendicular L2 L11
  coincident L6 P33
  perpendicular L6 L13
  coincident L6 P35
  perpendicular L13 L15
  coincident L2 P37
  perpendicular L2 L16
  dimension "d115" distance P29 P30 = 6
  dimension "d116" distance P29 P32 = 1
  dimension "d117" distance P33 P34 = 1
  dimension "d118" distance P33 P36 = 6
extrude "Extrude44" add sketch "Sketch16" profile of L2 L6 L9 L10 L11 L12 L13 L14 L15 L16 L17 along normal blind 3.5
sketch "Sketch17" plane through (-18, 0, 0) normal (-1, 0, 0) x axis (0, -1, 0)
  line L1 (16.5, 12) -> (16.5, 11)
  line L2 (-16.5, 12) -> (16.5, 12)
  line L3 (-16.5, 11) -> (-16.5, 12)
  line L4 (-10.5, 11) -> (-16.5, 11)
  line L5 (-4.5, 12) -> (-10.5, 12)
  line L6 (-4.5, 10) -> (-4.5, 12)
  line L7 (-10.5, 10) -> (-4.5, 10)
  line L8 (-10.5, 12) -> (-10.5, 10)
  line L9 (10.5, 12) -> (4.5, 12)
  line L10 (10.5, 10) -> (10.5, 12)
  line L11 (4.5, 10) -> (10.5, 10)
  line L12 (4.5, 12) -> (4.5, 10)
  line L13 (-10.5, 7.5) -> (-10.5, 11)
  line L14 (-4.5, 7.5) -> (-10.5, 7.5)
  line L15 (-4.5, 11) -> (-4.5, 7.5)
  line L16 (4.5, 11) -> (-4.5, 11)
  line L17 (4.5, 7.5) -> (4.5, 11)
  line L18 (10.5, 7.5) -> (4.5, 7.5)
  line L19 (10.5, 11) -> (10.5, 7.5)
  line L20 (16.5, 11) -> (10.5, 11)
  point P7 (-10.5, 12)
  point P11 (4.5, 12)
  point P8 (-4.5, 12)
  point P10 (-10.5, 10)
  point P12 (10.5, 12)
  point P14 (4.5, 10)
  horizontal L5
  vertical L6
  horizontal L7
  vertical L8
  coincident L2 P7
  horizontal L9
  vertical L10
  horizontal L11
  vertical L12
  coincident L2 P11
  dimension "d121" distance P7 P8 = 6
  dimension "d122" distance P7 P10 = 2
  dimension "d123" distance P11 P12 = 6
  dimension "d124" distance P11 P14 = 2
extrude "Extrude45" add sketch "Sketch17" profile of L2 L5 L6 L7 L8 L9 L10 L11 L12 along normal blind 2 taper -45
fillet "Fillet7" radius 0.4
move "Move11"
extrude "Extrude46" cut sketch "Sketch17" profile of L2 L5 L6 L7 L8 L9 L10 L11 L12 along normal blind 2 taper -45
chamfer "Chamfer1" distance 0.2
fillet "Fillet8" radius 86.45
move "Move12"
sketch "Sketch18" plane through (18, 0, 0) normal (1, 0, 0) x axis (0, 1, 0)
  line L1 (-16.5, 11) -> (-16.5, 12)
  line L2 (-8.6, 11) -> (-16.5, 11)
  line L3 (16.5, 12) -> (16.5, 11)
  line L4 (-16.5, 12) -> (16.5, 12)
  line L5 (-2.4, 12) -> (-8.6, 12)
  line L6 (-2.4, 10) -> (-2.4, 12)
  line L7 (-8.6, 10) -> (-2.4, 10)
  line L8 (-8.6, 12) -> (-8.6, 10)
  line L9 (8.6, 12) -> (2.4, 12)
  line L10 (8.6, 10) -> (8.6, 12)
  line L11 (2.4, 10) -> (8.6, 10)
  line L12 (2.4, 12) -> (2.4, 10)
  line L13 (-8.6, 7.5) -> (-8.6, 11)
  line L14 (-2.4, 7.5) -> (-8.6, 7.5)
  line L15 (-2.4, 11) -> (-2.4, 7.5)
  line L16 (2.4, 11) -> (-2.4, 11)
  line L17 (2.4, 7.5) -> (2.4, 11)
  line L18 (8.6, 7.5) -> (2.4, 7.5)
  line L19 (8.6, 11) -> (8.6, 7.5)
  line L20 (16.5, 11) -> (8.6, 11)
  point P7 (-8.6, 12)
  point P11 (2.4, 12)
  point P10 (-8.6, 10)
  point P14 (2.4, 10)
  horizontal L5
  vertical L6
  horizontal L7
  vertical L8
  coincident L4 P7
  horizontal L9
  vertical L10
  horizontal L11
  vertical L12
  coincident L4 P11
  dimension "d135" distance P7 P10 = 2
  dimension "d136" distance P11 P14 = 2
extrude "Extrude47" add sketch "Sketch18" profile of L4 L5 L6 L7 L8 L9 L10 L11 L12 along normal blind 2 taper -45
fillet "Fillet9" radius 0.4
extrude "Extrude48" cut sketch "Sketch18" profile of L4 L5 L6 L7 L8 L9 L10 L11 L12 along normal blind 2 taper -45
chamfer "Chamfer2" distance 0.2
fillet "Fillet10" radius 168.2
move "Move13"
sketch "Sketch19" plane through (0, 0, 14) normal (0, 0, 1) x axis (-1, 0, 0)
  line L1 (19, 17.5) -> (19, -17.5)
  line L2 (-12, 24.5) -> (12, 24.5)
  line L3 (-19, -17.5) -> (-19, 17.5)
  line L4 (12, -24.5) -> (-12, -24.5)
  line L5 (-13.6766, 12.6436) -> (-13.6766, -15.525)
  line L6 (13.9332, -15.525) -> (13.9332, 12.6436)
  line L7 (13.4719, -17.6526) -> (7.4719, -17.6526)
  line L8 (13.4719, -20.6526) -> (13.4719, -17.6526)
  line L9 (7.4719, -20.6526) -> (13.4719, -20.6526)
  line L10 (7.4719, -17.6526) -> (7.4719, -20.6526)
  line L11 (13.4719, -20.6526) -> (7.4719, -17.6526)
  line L12 (7.4719, -20.6526) -> (13.4719, -17.6526)
  line L13 (8.9719, -20.65) -> (11.9719, -20.65)
  line L14 (8.9719, -17.6553) -> (8.9719, -20.65)
  line L15 (11.9719, -17.6553) -> (8.9719, -17.6553)
  line L16 (11.9719, -20.65) -> (11.9719, -17.6553)
  line L17 (-9.9, -22.2) -> (-9.9, -18.2)
  line L18 (-12.9, -22.2) -> (-9.9, -22.2)
  line L19 (-12.9, -18.2) -> (-12.9, -22.2)
  line L20 (-9.9, -18.2) -> (-12.9, -18.2)
  line L21 (13.9332, 12.6436) -> (-13.6766, 12.6436)
  line L22 (-13.6766, -15.525) -> (13.9332, -15.525)
  line L23 (-10.4379, 21.1152) -> (-12.5679, 21.1152)
  line L24 (-10.3879, 18.9352) -> (-10.3879, 21.0652)
  line L25 (-12.5679, 18.8852) -> (-10.4379, 18.8852)
  line L26 (-12.6179, 21.0652) -> (-12.6179, 18.9352)
  arc A1 centre (12, -17.5) radius 7 clockwise from (19, -17.5) to (12, -24.5)
  arc A2 centre (12, 17.5) radius 7 clockwise from (12, 24.5) to (19, 17.5)
  arc A3 centre (-12, 17.5) radius 7 clockwise from (-19, 17.5) to (-12, 24.5)
  arc A4 centre (-12, -17.5) radius 7 clockwise from (-12, -24.5) to (-19, -17.5)
  circle C1 centre (-10.4379, 19.8852) radius 1
  circle C2 centre (-12.9379, 19.8852) radius 1
  circle C3 centre (-15.4379, 19.8852) radius 1
  circle C4 centre (-10.4379, 22.3852) radius 1
  circle C5 centre (-12.9379, 22.3852) radius 1
  circle C6 centre (-15.4379, 22.3852) radius 1
  circle C7 centre (-9.9, -19.2) radius 1
  circle C8 centre (-12.9, -19.2) radius 1
  circle C9 centre (-15.9, -19.2) radius 1
  circle C10 centre (-9.9, -21.7) radius 1
  circle C11 centre (-12.9, -21.7) radius 1
  circle C12 centre (-15.9, -21.7) radius 1
  arc A5 centre (-10.4379, 21.0652) radius 0.05 clockwise from (-10.4379, 21.1152) to (-10.3879, 21.0652)
  arc A6 centre (-10.4379, 18.9352) radius 0.05 clockwise from (-10.3879, 18.9352) to (-10.4379, 18.8852)
  arc A7 centre (-12.5679, 18.9352) radius 0.05 clockwise from (-12.5679, 18.8852) to (-12.6179, 18.9352)
  arc A8 centre (-12.5679, 21.0652) radius 0.05 clockwise from (-12.6179, 21.0652) to (-12.5679, 21.1152)
  point P34 (10.4719, -19.1526)
  point P32 (13.4719, -20.6526)
  point P33 (7.4719, -20.6526)
  point P31 (13.4719, -17.6526)
  horizontal L7
  perpendicular L7 L8
  parallel L7 L9
  parallel L8 L10
  coincident L11 P34
  coincident L12 P34
  dimension "d148" diameter C1 = 2
  dimension "d164" distance P32 P33 = 6
  dimension "d165" distance P31 P32 = 3
  dimension "d151" R-Pattern1-uDistance = -5
  dimension "d152" R-Pattern1-vDistance = 2.5
  dimension "d156" R-Pattern2-uDistance = -6
  dimension "d157" R-Pattern2-vDistance = -2.5
delete_face "DeleteFace1"
delete_face "DeleteFace2"
extrude "Extrude49" add of existing geometry blind 2.3
extrude "Extrude50" add of existing geometry blind 4
extrude "Extrude51" cut sketch "Sketch19" profile of C1 C2 C4 C5 C7 C8 C9 C10 C11 against normal blind 2
extrude "Extrude52" cut sketch "Sketch19" profile of L7 L8 L9 L10 against normal blind 1
sketch "Sketch20" plane through (0, 0, 12) normal (0, 0, -1) x axis (1, 0, 0)
  line L1 (13.6766, -15.525) -> (13.6766, 12.6436)
  line L2 (-13.9332, 12.6436) -> (-13.9332, -15.525)
  line L3 (17, 15.5) -> (17, -15.5)
  line L4 (-10, 22.5) -> (9.4445, 22.5)
  line L5 (-17, -15.5) -> (-17, 15.5)
  line L6 (9.3, -22.5) -> (-10, -22.5)
  line L7 (-6.5, -18) -> (0, -18)
  line L8 (-6.5, -21) -> (-6.5, -18)
  line L9 (6.5, -21) -> (-6.5, -21)
  line L10 (6.5, -18) -> (6.5, -21)
  line L11 (0, -18) -> (6.5, -18)
  line L12 (-11.9719, -20.65) -> (-8.9719, -20.65)
  line L13 (-11.9719, -17.6553) -> (-11.9719, -20.65)
  line L14 (-8.9719, -17.6553) -> (-11.9719, -17.6553)
  line L15 (-8.9719, -20.65) -> (-8.9719, -17.6553)
  line L16 (-13.9332, -15.525) -> (13.6766, -15.525)
  line L17 (13.6766, 12.6436) -> (-13.9332, 12.6436)
  line L18 (12.034, -22.2) -> (12.0273, -22.2)
  arc A1 centre (10, -15.5) radius 7 clockwise from (15.3386, -20.0276) to (13.8382, -21.3539)
  arc A2 centre (10, 15.5) radius 7 clockwise from (13.5033, 21.5603) to (17, 15.5)
  arc A3 centre (-10, 15.5) radius 7 clockwise from (-17, 15.5) to (-10, 22.5)
  arc A4 centre (-10, -15.5) radius 7 clockwise from (-10, -22.5) to (-17, -15.5)
  circle C1 centre (9.9, -19.2) radius 1
  circle C2 centre (10.4379, 19.8852) radius 1
  circle C3 centre (12.9, -19.2) radius 1
  circle C4 centre (12.9379, 19.8852) radius 1
  arc A5 centre (12.9, -21.7) radius 1 clockwise from (12.034, -22.2) to (13.8382, -21.3539)
  arc A6 centre (15.9, -19.2) radius 1 clockwise from (15.3386, -20.0276) to (16.4005, -18.3343)
  arc A7 centre (10, -15.5) radius 7 clockwise from (17, -15.5) to (16.4005, -18.3343)
  arc A8 centre (12.9379, 22.3852) radius 1 clockwise from (13.5033, 21.5603) to (11.9512, 22.2226)
  arc A9 centre (10, 15.5) radius 7 clockwise from (11.4373, 22.3508) to (11.9512, 22.2226)
  arc A10 centre (10.4379, 22.3852) radius 1 clockwise from (11.4373, 22.3508) to (9.4445, 22.5)
  arc A11 centre (9.9, -21.7) radius 1 clockwise from (9.3, -22.5) to (10.5255, -22.4802)
  arc A12 centre (10, -15.5) radius 7 clockwise from (12.0273, -22.2) to (10.5255, -22.4802)
  horizontal L7
  perpendicular L7 L8
  perpendicular L8 L9
  perpendicular L9 L10
  perpendicular L8 L11
extrude "Extrude56" add sketch "Sketch20" profile of L7 L8 L9 L10 L11 along normal blind 3
extrude "Extrude57" add of existing geometry blind 0.5
sketch "Sketch22" plane through (0, 18, 0) normal (0, -1, 0) x axis (1, 0, 0)
  line L1 (-6.5, 8.5) -> (-6.5, 12)
  line L2 (6.5, 8.5) -> (-6.5, 8.5)
  line L3 (6.5, 12) -> (6.5, 8.5)
  line L4 (-5, 9) -> (5, 9)
  line L5 (-5, 11) -> (-5, 9)
  line L6 (5, 11) -> (-5, 11)
  line L7 (5, 9) -> (5, 11)
  line L8 (-5, 11) -> (5, 9)
  line L9 (5, 11) -> (-5, 9)
  line L10 (-6.5, 12) -> (6.5, 12)
  point P10 (0, 10)
  horizontal L4
  perpendicular L4 L5
  parallel L4 L6
  parallel L5 L7
  coincident L8 P10
  coincident L9 P10
extrude "Extrude58" cut sketch "Sketch22" profile of L4 L5 L6 L7 against normal blind 2
extrude "Extrude59" new body of existing geometry blind 6 bodies "Pana"
extrude "Extrude60" cut of existing geometry blind -0.1
extrude "Extrude61" cut of existing geometry blind -0.2
extrude "Extrude62" add of existing geometry blind 1
extrude "Extrude63" add of existing geometry blind 1
extrude "Extrude64" add of existing geometry blind 0.2
extrude "Extrude65" add of existing geometry blind 0.1
extrude "Extrude66" cut of existing geometry blind -0.1
extrude "Extrude67" add of existing geometry blind 0.1
extrude "Extrude68" cut of existing geometry blind -0.1
extrude "Extrude69" cut of existing geometry blind -0.1
extrude "Extrude70" cut of existing geometry blind -18
extrude "Extrude71" cut of existing geometry blind -0.2
extrude "Extrude72" cut of existing geometry blind -0.2
extrude "Extrude73" add of existing geometry blind 0.1
extrude "Extrude74" add of existing geometry blind 0.1
extrude "Extrude75" cut of existing geometry blind -1
extrude "Extrude76" add of existing geometry blind 0.5
extrude "Extrude77" cut of existing geometry blind -0.5
extrude "Extrude78" cut of existing geometry blind -0.5
extrude "Extrude79" add of existing geometry blind 0.5
fillet "Fillet11" radius 1
fillet "Fillet12" radius 1
extrude "Extrude80" add of existing geometry blind 0.15
extrude "Extrude81" cut of existing geometry blind 10
sketch "Sketch23" plane through (0, 0, 10) normal (0, 0, -1) x axis (1, 0, 0)
  line L1 (-15.885, 19.2904) -> (-16.0414, 19.2904)
  line L2 (10, 22.5) -> (-10, 22.5)
  line L3 (17, 8.6) -> (17, 15.5)
  line L4 (18, 8.6) -> (17, 8.6)
  line L5 (18, 16.5) -> (18, 8.6)
  line L6 (-11, 23.5) -> (11, 23.5)
  line L7 (-18, 10.5) -> (-18, 16.5)
  line L8 (-17, 10.5) -> (-18, 10.5)
  line L9 (-17, 15.5) -> (-17, 10.5)
  line L10 (-16.0414, 19.2904) -> (-16.0414, 19.0358)
  line L11 (-15.885, 19.2904) -> (-17.4198, 19.2904)
  line L12 (-15.1041, 20.2904) -> (-16.885, 20.2904)
  line L13 (17.4198, 19.2904) -> (15.885, 19.2904)
  line L14 (15.1041, 20.2904) -> (15.885, 20.2904)
  line L15 (16.885, 20.2904) -> (15.885, 20.2904)
  arc A1 centre (-10, 15.5) radius 7 clockwise from (-15.885, 19.2904) to (-10, 22.5)
  arc A2 centre (10, 15.5) radius 7 clockwise from (10, 22.5) to (17, 15.5)
  arc A3 centre (11, 16.5) radius 7 clockwise from (11, 23.5) to (18, 16.5)
  arc A4 centre (-11, 16.5) radius 7 clockwise from (-18, 16.5) to (-11, 23.5)
  arc A5 centre (-10, 15.5) radius 7 clockwise from (-17, 15.5) to (-16.0414, 19.0358)
  point P21 (-17.4198, 19.2904)
  point P3 (-15.885, 19.2904)
  point P22 (-15.885, 19.2904)
  point P23 (-16.885, 20.2904)
  point P24 (-15.1041, 20.2904)
  point P25 (15.885, 19.2904)
  point P26 (17.4198, 19.2904)
  point P28 (15.1041, 20.2904)
  point P29 (16.885, 20.2904)
  coincident A4 P21
  coincident P3 P22
  perpendicular L10 L11
  coincident A4 P23
  coincident A1 P24
  coincident A2 P25
  coincident A3 P26
  coincident A2 P28
  coincident A3 P29
extrude "Extrude82" cut sketch "Sketch23" profile of L1 A1 A2 A3 A4 L11 L12 L13 L14 L15 against normal blind 2
extrude "Extrude83" cut of existing geometry blind -1.016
